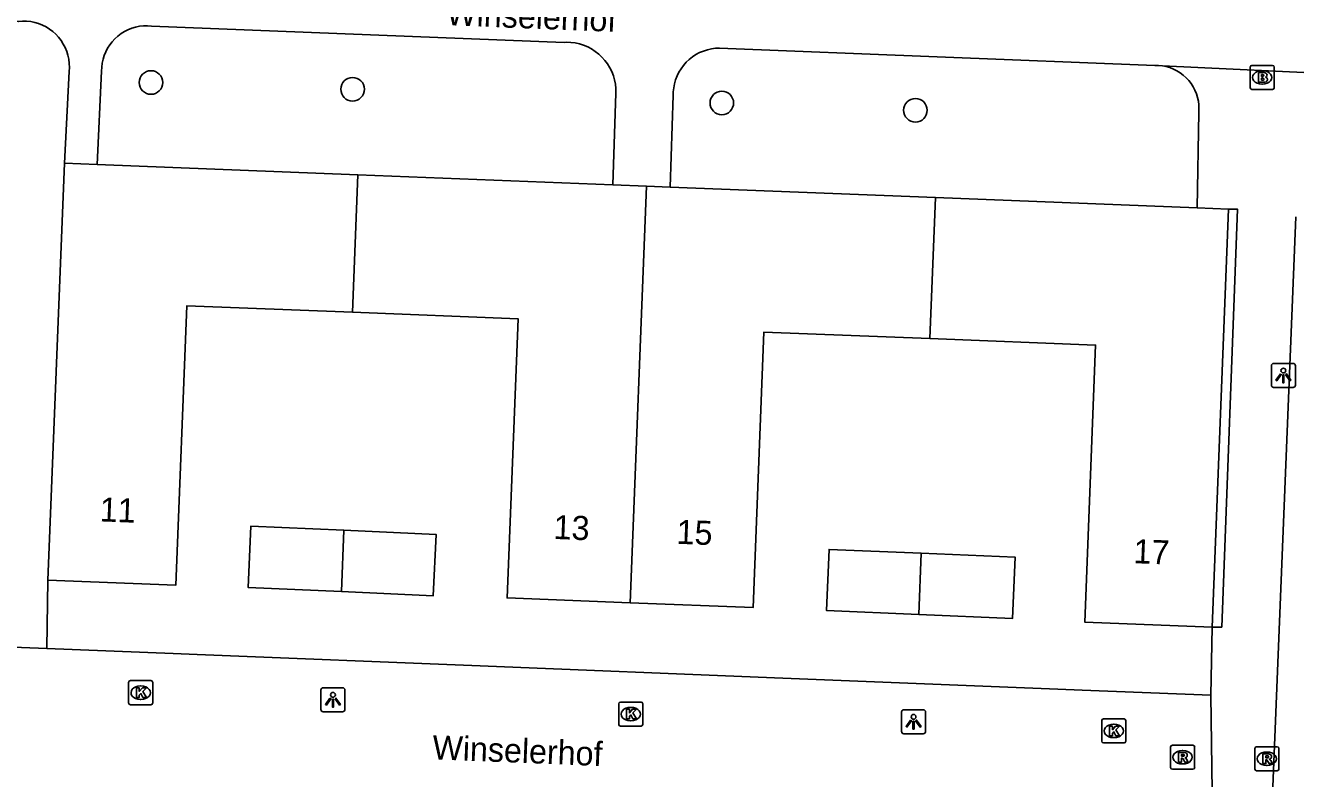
# Model space of a CAD drawing. Extents: x 160787 to 161428, y 386828 to 387483.
# Drawn here: x 161039.4 to 161092.1, y 387016.5 to 387047.7 of the extents above; entities that cross this region are included whole.
import ezdxf

# ---------------------------------------------------------------- set-up
doc = ezdxf.new("R2010")
doc.units = 0
for name, color, linetype in [('IMGEO_Boom', 7, 'Continuous'), ('IMGEO_Brandkraan', 7, 'Continuous'), ('IMGEO_Groenvoorziening', 7, 'Continuous'), ('IMGEO_Kolk', 7, 'Continuous'), ('IMGEO_Lichtpunt', 7, 'Continuous'), ('IMGEO_Openbare_ruimte_label', 7, 'Continuous'), ('IMGEO_Pand', 7, 'Continuous'), ('IMGEO_Pand_nummerreeks', 7, 'Continuous'), ('IMGEO_Rioolput', 7, 'Continuous'), ('IMGEO_Voetpad_open', 7, 'Continuous')]:
    doc.layers.add(name, color=color, linetype=linetype)

msp = doc.modelspace()

# ---------------------------------------------------------------- linework, layer by layer
at = {"layer": 'IMGEO_Boom'}
for centre in [(161044.621, 387045.348), (161052.986, 387045.068), (161068.308, 387044.499), (161076.343, 387044.195)]:
    msp.add_circle(centre, 0.489, dxfattribs=at)
at = {"layer": 'IMGEO_Brandkraan'}
for p, q in [((161090.233, 387045.132), (161090.233, 387045.984)), ((161090.308, 387046.058), (161091.16, 387046.058)), ((161091.234, 387045.984), (161091.234, 387045.132)), ((161090.721, 387045.838), (161090.746, 387045.838)), ((161091.16, 387045.058), (161090.308, 387045.058)), ((161090.744, 387045.278), (161090.719, 387045.278))]:
    msp.add_line(p, q, dxfattribs=at)
for points in [[(161090.233, 387045.132), (161090.233, 387045.984)], [(161090.308, 387046.058), (161091.16, 387046.058)], [(161091.234, 387045.984), (161091.234, 387045.132)], [(161090.581, 387045.758), (161090.581, 387045.358), (161090.794, 387045.358)], [(161090.812, 387045.758), (161090.581, 387045.758)], [(161090.76, 387045.677), (161090.706, 387045.677), (161090.706, 387045.601)], [(161090.706, 387045.601), (161090.759, 387045.601)], [(161090.768, 387045.525), (161090.706, 387045.525), (161090.706, 387045.444)], [(161090.706, 387045.444), (161090.768, 387045.444)], [(161091.16, 387045.058), (161090.308, 387045.058)]]:
    msp.add_lwpolyline(points, dxfattribs=at)
for centre, radius, start, end in [((161090.31, 387045.982), 0.0765, 91.552, 178.448), ((161090.31, 387045.982), 0.0765, 91.552, 178.448), ((161091.158, 387045.982), 0.0765, 1.552, 88.448), ((161091.158, 387045.982), 0.0765, 1.552, 88.448), ((161090.761, 387045.639), 0.0379, 267.8285, 90.9355), ((161090.769, 387045.484), 0.0404, 269.8759, 90.5077), ((161090.8, 387045.609), 0.251, 268.6676, 293.5347), ((161090.816, 387045.613), 0.145, 59.4692, 91.5367), ((161090.841, 387045.66), 0.0922, 285.5137, 58.1501), ((161090.846, 387045.468), 0.105, 301.3115, 78.989), ((161090.31, 387045.134), 0.0765, 181.552, 268.448), ((161090.31, 387045.134), 0.0765, 181.552, 268.448), ((161091.158, 387045.134), 0.0765, 271.552, 358.448), ((161091.158, 387045.134), 0.0765, 271.552, 358.448)]:
    msp.add_arc(centre, radius, start, end, dxfattribs=at)
for centre, major_axis, ratio, start_param, end_param in [((161090.72, 387045.558), (-0.387, 0.002), 0.722429, 4.712389, 7.853982), ((161090.745, 387045.558), (-0.39, 0.002), 0.717154, 1.570796, 4.712389)]:
    msp.add_ellipse(centre, major_axis=major_axis, ratio=ratio, start_param=start_param, end_param=end_param, dxfattribs=at)
at = {"layer": 'IMGEO_Groenvoorziening'}
msp.add_lwpolyline([(161040.347, 387024.697), (161040.297, 387021.856)], dxfattribs=at)
at = {"layer": 'IMGEO_Kolk'}
for p, q in [((161043.693, 387019.597), (161043.693, 387020.449)), ((161043.768, 387020.523), (161044.62, 387020.523)), ((161044.181, 387020.303), (161044.206, 387020.303)), ((161044.694, 387020.449), (161044.694, 387019.597)), ((161044.62, 387019.523), (161043.768, 387019.523)), ((161044.204, 387019.743), (161044.179, 387019.743)), ((161064.029, 387018.708), (161064.029, 387019.56)), ((161064.104, 387019.634), (161064.956, 387019.634)), ((161065.03, 387019.56), (161065.03, 387018.708)), ((161064.517, 387019.414), (161064.542, 387019.414)), ((161064.956, 387018.634), (161064.104, 387018.634)), ((161064.54, 387018.854), (161064.515, 387018.854)), ((161084.072, 387018.01), (161084.072, 387018.862)), ((161084.147, 387018.936), (161084.999, 387018.936)), ((161084.56, 387018.716), (161084.585, 387018.716)), ((161085.073, 387018.862), (161085.073, 387018.01)), ((161084.999, 387017.936), (161084.147, 387017.936)), ((161084.583, 387018.156), (161084.558, 387018.156))]:
    msp.add_line(p, q, dxfattribs=at)
for points in [[(161043.693, 387019.597), (161043.693, 387020.449)], [(161043.768, 387020.523), (161044.62, 387020.523)], [(161044.014, 387020.223), (161044.137, 387020.223), (161044.137, 387020.072), (161044.267, 387020.223), (161044.431, 387020.223), (161044.285, 387020.072), (161044.438, 387019.823), (161044.286, 387019.823), (161044.201, 387019.987), (161044.137, 387019.92), (161044.137, 387019.823), (161044.014, 387019.823), (161044.014, 387020.223)], [(161044.694, 387020.449), (161044.694, 387019.597)], [(161044.62, 387019.523), (161043.768, 387019.523)], [(161064.029, 387018.708), (161064.029, 387019.56)], [(161064.104, 387019.634), (161064.956, 387019.634)], [(161065.03, 387019.56), (161065.03, 387018.708)], [(161064.35, 387019.334), (161064.473, 387019.334), (161064.473, 387019.183), (161064.603, 387019.334), (161064.767, 387019.334), (161064.621, 387019.183), (161064.774, 387018.934), (161064.622, 387018.934), (161064.537, 387019.098), (161064.473, 387019.031), (161064.473, 387018.934), (161064.35, 387018.934), (161064.35, 387019.334)], [(161064.956, 387018.634), (161064.104, 387018.634)], [(161084.072, 387018.01), (161084.072, 387018.862)], [(161084.147, 387018.936), (161084.999, 387018.936)], [(161084.393, 387018.636), (161084.516, 387018.636), (161084.516, 387018.485), (161084.646, 387018.636), (161084.81, 387018.636), (161084.664, 387018.485), (161084.817, 387018.236), (161084.665, 387018.236), (161084.58, 387018.4), (161084.516, 387018.333), (161084.516, 387018.236), (161084.393, 387018.236), (161084.393, 387018.636)], [(161085.073, 387018.862), (161085.073, 387018.01)], [(161084.999, 387017.936), (161084.147, 387017.936)]]:
    msp.add_lwpolyline(points, dxfattribs=at)
for centre, start, end in [((161043.77, 387020.447), 91.552, 178.448), ((161043.77, 387020.447), 91.552, 178.448), ((161044.618, 387020.447), 1.552, 88.448), ((161044.618, 387020.447), 1.552, 88.448), ((161043.77, 387019.599), 181.552, 268.448), ((161043.77, 387019.599), 181.552, 268.448), ((161044.618, 387019.599), 271.552, 358.448), ((161044.618, 387019.599), 271.552, 358.448), ((161064.106, 387019.558), 91.552, 178.448), ((161064.106, 387019.558), 91.552, 178.448), ((161064.954, 387019.558), 1.552, 88.448), ((161064.954, 387019.558), 1.552, 88.448), ((161064.106, 387018.71), 181.552, 268.448), ((161064.106, 387018.71), 181.552, 268.448), ((161064.954, 387018.71), 271.552, 358.448), ((161064.954, 387018.71), 271.552, 358.448), ((161084.149, 387018.86), 91.552, 178.448), ((161084.149, 387018.86), 91.552, 178.448), ((161084.997, 387018.86), 1.552, 88.448), ((161084.997, 387018.86), 1.552, 88.448), ((161084.149, 387018.012), 181.552, 268.448), ((161084.149, 387018.012), 181.552, 268.448), ((161084.997, 387018.012), 271.552, 358.448), ((161084.997, 387018.012), 271.552, 358.448)]:
    msp.add_arc(centre, 0.0765, start, end, dxfattribs=at)
for centre, major_axis, ratio, start_param, end_param in [((161044.18, 387020.023), (-0.387, 0.002), 0.722429, 4.712389, 7.853982), ((161044.205, 387020.023), (-0.39, 0.002), 0.717154, 1.570796, 4.712389), ((161064.516, 387019.134), (-0.387, 0.002), 0.722429, 4.712389, 7.853982), ((161064.541, 387019.134), (-0.39, 0.002), 0.717154, 1.570796, 4.712389), ((161084.559, 387018.436), (-0.387, 0.002), 0.722429, 4.712389, 7.853982), ((161084.584, 387018.436), (-0.39, 0.002), 0.717154, 1.570796, 4.712389)]:
    msp.add_ellipse(centre, major_axis=major_axis, ratio=ratio, start_param=start_param, end_param=end_param, dxfattribs=at)
at = {"layer": 'IMGEO_Lichtpunt'}
for p, q in [((161091.113, 387033.594), (161091.113, 387032.787)), ((161091.113, 387033.594), (161091.113, 387032.787)), ((161092.015, 387033.689), (161091.207, 387033.689)), ((161092.015, 387033.689), (161091.207, 387033.689)), ((161092.109, 387032.787), (161092.109, 387033.594)), ((161092.109, 387032.787), (161092.109, 387033.594)), ((161091.207, 387032.693), (161092.015, 387032.693)), ((161091.207, 387032.693), (161092.015, 387032.693)), ((161051.673, 387020.134), (161051.673, 387019.327)), ((161051.673, 387020.134), (161051.673, 387019.327)), ((161052.575, 387020.229), (161051.767, 387020.229)), ((161052.575, 387020.229), (161051.767, 387020.229)), ((161052.669, 387019.327), (161052.669, 387020.134)), ((161052.669, 387019.327), (161052.669, 387020.134)), ((161051.767, 387019.233), (161052.575, 387019.233)), ((161051.767, 387019.233), (161052.575, 387019.233)), ((161075.766, 387019.221), (161075.766, 387018.414)), ((161075.766, 387019.221), (161075.766, 387018.414)), ((161076.668, 387019.316), (161075.86, 387019.316)), ((161076.668, 387019.316), (161075.86, 387019.316)), ((161076.762, 387018.414), (161076.762, 387019.221)), ((161076.762, 387018.414), (161076.762, 387019.221)), ((161075.86, 387018.32), (161076.668, 387018.32)), ((161075.86, 387018.32), (161076.668, 387018.32))]:
    msp.add_line(p, q, dxfattribs=at)
for points in [[(161091.487, 387033.258), (161091.526, 387033.23), (161091.338, 387032.968), (161091.3, 387032.995), (161091.487, 387033.258)], [(161091.589, 387033.21), (161091.636, 387033.21), (161091.636, 387032.888), (161091.589, 387032.888), (161091.589, 387033.21)], [(161091.699, 387033.23), (161091.737, 387033.257), (161091.924, 387032.995), (161091.885, 387032.967), (161091.699, 387033.23)], [(161052.047, 387019.798), (161052.086, 387019.77), (161051.898, 387019.508), (161051.86, 387019.535), (161052.047, 387019.798)], [(161052.149, 387019.75), (161052.196, 387019.75), (161052.196, 387019.428), (161052.149, 387019.428), (161052.149, 387019.75)], [(161052.259, 387019.77), (161052.297, 387019.797), (161052.484, 387019.535), (161052.445, 387019.507), (161052.259, 387019.77)], [(161076.14, 387018.885), (161076.179, 387018.857), (161075.991, 387018.595), (161075.953, 387018.622), (161076.14, 387018.885)], [(161076.242, 387018.837), (161076.289, 387018.837), (161076.289, 387018.515), (161076.242, 387018.515), (161076.242, 387018.837)], [(161076.352, 387018.857), (161076.39, 387018.884), (161076.577, 387018.622), (161076.538, 387018.594), (161076.352, 387018.857)]]:
    msp.add_lwpolyline(points, dxfattribs=at)
for centre in [(161091.612, 387033.392), (161052.172, 387019.932), (161076.265, 387019.019)]:
    msp.add_circle(centre, 0.0994, dxfattribs=at)
for centre, start, end in [((161091.207, 387033.594), 90, 180), ((161091.207, 387033.594), 90, 180), ((161092.015, 387033.594), 0, 90), ((161092.015, 387033.594), 0, 90), ((161091.207, 387032.787), 180, 270), ((161091.207, 387032.787), 180, 270), ((161092.015, 387032.787), 270, 0), ((161092.015, 387032.787), 270, 360), ((161051.767, 387020.134), 90, 180), ((161051.767, 387020.134), 90, 180), ((161052.575, 387020.134), 0, 90), ((161052.575, 387020.134), 0, 90), ((161051.767, 387019.327), 180, 270), ((161051.767, 387019.327), 180, 270), ((161052.575, 387019.327), 270, 0), ((161052.575, 387019.327), 270, 360), ((161075.86, 387019.221), 90, 180), ((161075.86, 387019.221), 90, 180), ((161076.668, 387019.221), 0, 90), ((161076.668, 387019.221), 0, 90), ((161075.86, 387018.414), 180, 270), ((161075.86, 387018.414), 180, 270), ((161076.668, 387018.414), 270, 0), ((161076.668, 387018.414), 270, 360)]:
    msp.add_arc(centre, 0.0946, start, end, dxfattribs=at)
at = {"layer": 'IMGEO_Pand'}
for points in [[(161041.029, 387042.001), (161040.347, 387024.697)], [(161041.029, 387042.001), (161042.387, 387041.947)], [(161042.387, 387041.947), (161053.207, 387041.521)], [(161052.982, 387035.81), (161053.207, 387041.521)], [(161053.207, 387041.521), (161063.786, 387041.104)], [(161063.786, 387041.104), (161065.182, 387041.049)], [(161064.5, 387023.758), (161065.182, 387041.049)], [(161065.182, 387041.049), (161066.166, 387041.01)], [(161077.169, 387040.577), (161066.166, 387041.01)], [(161077.169, 387040.577), (161076.938, 387034.717)], [(161088.036, 387040.148), (161077.169, 387040.577)], [(161088.036, 387040.148), (161089.337, 387040.097)], [(161088.653, 387022.747), (161089.337, 387040.097)], [(161040.347, 387024.697), (161045.654, 387024.488), (161046.111, 387036.081), (161052.982, 387035.81)], [(161052.982, 387035.81), (161059.855, 387035.539), (161059.398, 387023.959), (161064.5, 387023.758)], [(161064.5, 387023.758), (161069.606, 387023.557), (161070.057, 387034.988), (161076.938, 387034.717)], [(161076.938, 387034.717), (161083.821, 387034.446), (161083.368, 387022.956), (161088.653, 387022.747)], [(161052.525, 387024.218), (161048.651, 387024.394), (161048.767, 387026.938), (161052.626, 387026.762)], [(161052.626, 387026.762), (161056.451, 387026.588), (161056.335, 387024.044), (161052.525, 387024.218)], [(161052.626, 387026.762), (161052.525, 387024.218)], [(161076.487, 387023.268), (161072.653, 387023.428), (161072.759, 387025.972), (161076.587, 387025.812)], [(161076.587, 387025.812), (161080.481, 387025.65), (161080.375, 387023.106), (161076.487, 387023.268)], [(161076.587, 387025.812), (161076.487, 387023.268)]]:
    msp.add_lwpolyline(points, dxfattribs=at)
at = {"layer": 'IMGEO_Rioolput'}
for p, q in [((161086.929, 387016.918), (161086.929, 387017.77)), ((161087.004, 387017.844), (161087.856, 387017.844)), ((161087.417, 387017.624), (161087.442, 387017.624)), ((161087.93, 387017.77), (161087.93, 387016.918)), ((161090.426, 387016.854), (161090.426, 387017.706)), ((161090.501, 387017.78), (161091.353, 387017.78)), ((161090.914, 387017.56), (161090.939, 387017.56)), ((161091.427, 387017.706), (161091.427, 387016.854)), ((161087.44, 387017.064), (161087.415, 387017.064)), ((161090.937, 387017), (161090.912, 387017)), ((161087.856, 387016.844), (161087.004, 387016.844)), ((161091.353, 387016.78), (161090.501, 387016.78))]:
    msp.add_line(p, q, dxfattribs=at)
for points in [[(161086.929, 387016.918), (161086.929, 387017.77)], [(161087.004, 387017.844), (161087.856, 387017.844)], [(161087.518, 387017.542), (161087.266, 387017.544), (161087.266, 387017.144)], [(161087.444, 387017.463), (161087.39, 387017.463), (161087.39, 387017.382)], [(161087.39, 387017.382), (161087.442, 387017.382)], [(161087.93, 387017.77), (161087.93, 387016.918)], [(161090.426, 387016.854), (161090.426, 387017.706)], [(161090.501, 387017.78), (161091.353, 387017.78)], [(161091.015, 387017.478), (161090.763, 387017.48), (161090.763, 387017.08)], [(161090.941, 387017.399), (161090.887, 387017.399), (161090.887, 387017.318)], [(161091.427, 387017.706), (161091.427, 387016.854)], [(161087.266, 387017.144), (161087.39, 387017.144), (161087.39, 387017.306), (161087.401, 387017.306)], [(161087.448, 387017.277), (161087.519, 387017.144), (161087.659, 387017.144), (161087.594, 387017.27)], [(161090.763, 387017.08), (161090.887, 387017.08), (161090.887, 387017.242), (161090.898, 387017.242)], [(161090.887, 387017.318), (161090.939, 387017.318)], [(161090.945, 387017.213), (161091.016, 387017.08), (161091.156, 387017.08), (161091.091, 387017.206)], [(161087.856, 387016.844), (161087.004, 387016.844)], [(161091.353, 387016.78), (161090.501, 387016.78)]]:
    msp.add_lwpolyline(points, dxfattribs=at)
for centre, radius, start, end in [((161087.006, 387017.768), 0.0765, 91.552, 178.448), ((161087.006, 387017.768), 0.0765, 91.552, 178.448), ((161087.426, 387017.571), 0.19, 274.7715, 282.9687), ((161087.45, 387017.367), 0.0964, 77.0061, 93.1865), ((161087.464, 387017.424), 0.0378, 276.6634, 79.6772), ((161087.517, 387017.432), 0.109, 350.3612, 89.416), ((161087.515, 387017.432), 0.112, 277.5842, 350.9817), ((161087.854, 387017.768), 0.0765, 1.552, 88.448), ((161087.854, 387017.768), 0.0765, 1.552, 88.448), ((161090.503, 387017.704), 0.0765, 91.552, 178.448), ((161090.503, 387017.704), 0.0765, 91.552, 178.448), ((161090.947, 387017.303), 0.0964, 77.0061, 93.1865), ((161090.961, 387017.36), 0.0378, 276.6634, 79.6772), ((161091.014, 387017.368), 0.109, 350.3612, 89.416), ((161091.351, 387017.704), 0.0765, 1.552, 88.448), ((161091.351, 387017.704), 0.0765, 1.552, 88.448), ((161087.006, 387016.92), 0.0765, 181.552, 268.448), ((161087.006, 387016.92), 0.0765, 181.552, 268.448), ((161087.4, 387017.253), 0.0533, 26.0293, 88.6989), ((161087.499, 387017.217), 0.108, 29.5134, 73.7905), ((161087.854, 387016.92), 0.0765, 271.552, 358.448), ((161087.854, 387016.92), 0.0765, 271.552, 358.448), ((161090.503, 387016.856), 0.0765, 181.552, 268.448), ((161090.503, 387016.856), 0.0765, 181.552, 268.448), ((161090.897, 387017.189), 0.0533, 26.0293, 88.6989), ((161090.923, 387017.507), 0.19, 274.7715, 282.9687), ((161091.012, 387017.368), 0.112, 277.5842, 350.9817), ((161090.996, 387017.153), 0.108, 29.5134, 73.7905), ((161091.351, 387016.856), 0.0765, 271.552, 358.448), ((161091.351, 387016.856), 0.0765, 271.552, 358.448)]:
    msp.add_arc(centre, radius, start, end, dxfattribs=at)
for centre, major_axis, ratio, start_param, end_param in [((161087.416, 387017.344), (-0.387, 0.002), 0.722429, 4.712389, 7.853982), ((161087.441, 387017.344), (-0.39, 0.002), 0.717154, 1.570796, 4.712389), ((161090.913, 387017.28), (-0.387, 0.002), 0.722429, 4.712389, 7.853982), ((161090.938, 387017.28), (-0.39, 0.002), 0.717154, 1.570796, 4.712389)]:
    msp.add_ellipse(centre, major_axis=major_axis, ratio=ratio, start_param=start_param, end_param=end_param, dxfattribs=at)
at = {"layer": 'IMGEO_Voetpad_open'}
for points in [[(161036.051, 387048.02), (161039.112, 387047.885), (161039.123, 387047.886), (161039.293, 387047.898), (161039.462, 387047.894), (161039.631, 387047.876), (161039.797, 387047.842), (161039.96, 387047.793), (161040.118, 387047.731), (161040.269, 387047.654), (161040.413, 387047.564), (161040.549, 387047.462), (161040.674, 387047.348), (161040.789, 387047.223), (161040.893, 387047.088), (161040.984, 387046.945), (161041.062, 387046.794), (161041.126, 387046.637), (161041.175, 387046.475), (161041.21, 387046.309), (161041.23, 387046.14), (161041.235, 387045.97), (161041.225, 387045.801), (161041.029, 387042.001)], [(161042.387, 387041.947), (161042.574, 387045.815), (161042.579, 387045.983), (161042.598, 387046.148), (161042.633, 387046.31), (161042.681, 387046.469), (161042.744, 387046.622), (161042.82, 387046.77), (161042.909, 387046.91), (161043.01, 387047.042), (161043.123, 387047.164), (161043.245, 387047.275), (161043.378, 387047.375), (161043.519, 387047.463), (161043.667, 387047.538), (161043.821, 387047.599), (161043.98, 387047.647), (161044.143, 387047.68), (161044.308, 387047.698), (161044.473, 387047.701), (161044.639, 387047.69), (161061.76, 387047.014), (161061.859, 387047.017), (161062.041, 387047.01), (161062.222, 387046.987), (161062.4, 387046.948), (161062.575, 387046.893), (161062.743, 387046.823), (161062.905, 387046.738), (161063.058, 387046.638), (161063.202, 387046.526), (161063.335, 387046.401), (161063.456, 387046.265), (161063.565, 387046.118), (161063.661, 387045.963), (161063.742, 387045.799), (161063.808, 387045.629), (161063.858, 387045.453), (161063.893, 387045.274), (161063.912, 387045.093), (161063.914, 387044.91), (161063.786, 387041.104)], [(161066.166, 387041.01), (161066.293, 387044.826), (161066.295, 387044.955), (161066.312, 387045.126), (161066.344, 387045.295), (161066.391, 387045.46), (161066.452, 387045.62), (161066.528, 387045.774), (161066.617, 387045.921), (161066.718, 387046.059), (161066.832, 387046.188), (161066.957, 387046.306), (161067.091, 387046.412), (161067.235, 387046.506), (161067.387, 387046.586), (161067.545, 387046.653), (161067.708, 387046.706), (161067.875, 387046.743), (161068.046, 387046.766), (161068.217, 387046.773), (161086.278, 387046.059), (161086.433, 387046.056), (161086.592, 387046.04)], [(161094.218, 387045.676), (161086.592, 387046.04)], [(161086.592, 387046.04), (161086.748, 387046.009), (161086.902, 387045.964), (161087.05, 387045.906), (161087.193, 387045.834), (161087.329, 387045.75), (161087.457, 387045.655), (161087.576, 387045.548), (161087.684, 387045.431), (161087.782, 387045.305), (161087.869, 387045.171), (161087.942, 387045.029), (161088.003, 387044.882), (161088.051, 387044.729), (161088.085, 387044.573), (161088.104, 387044.415), (161088.11, 387044.255), (161088.101, 387044.096), (161088.036, 387040.148)], [(161089.337, 387040.097), (161089.703, 387040.094), (161089.055, 387022.743), (161088.653, 387022.747)], [(161092.128, 387039.776), (161090.524, 387000), (161090.045, 386988.116), (161088.04, 386938.415)], [(161088.653, 387022.747), (161088.605, 387019.918)], [(161040.297, 387021.856), (161035.04, 387022.067)], [(161088.605, 387019.918), (161083.257, 387020.133), (161082.258, 387020.173), (161070.491, 387020.645), (161069.492, 387020.685), (161059.285, 387021.094), (161058.286, 387021.134), (161046.541, 387021.605), (161045.542, 387021.645), (161040.297, 387021.856)], [(161088.605, 387019.918), (161088.679, 387013.929)]]:
    msp.add_lwpolyline(points, dxfattribs=at)

# ---------------------------------------------------------------- texts
at = {"layer": 'IMGEO_Openbare_ruimte_label'}
for p in [(161056.86, 387047.729), (161056.283, 387017.259)]:
    msp.add_text('Winselerhof', height=1, rotation=357.7071, dxfattribs=at).set_placement(p)
at = {"layer": 'IMGEO_Pand_nummerreeks'}
for s, rotation, p in [('11', 357.7447, (161042.479, 387027.134)), ('13', 357.7448, (161061.315, 387026.405)), ('15', 357.7448, (161066.419, 387026.204)), ('17', 357.7354, (161085.376, 387025.398))]:
    msp.add_text(s, height=1, rotation=rotation, dxfattribs=at).set_placement(p)

doc.saveas('drawing.dxf')
